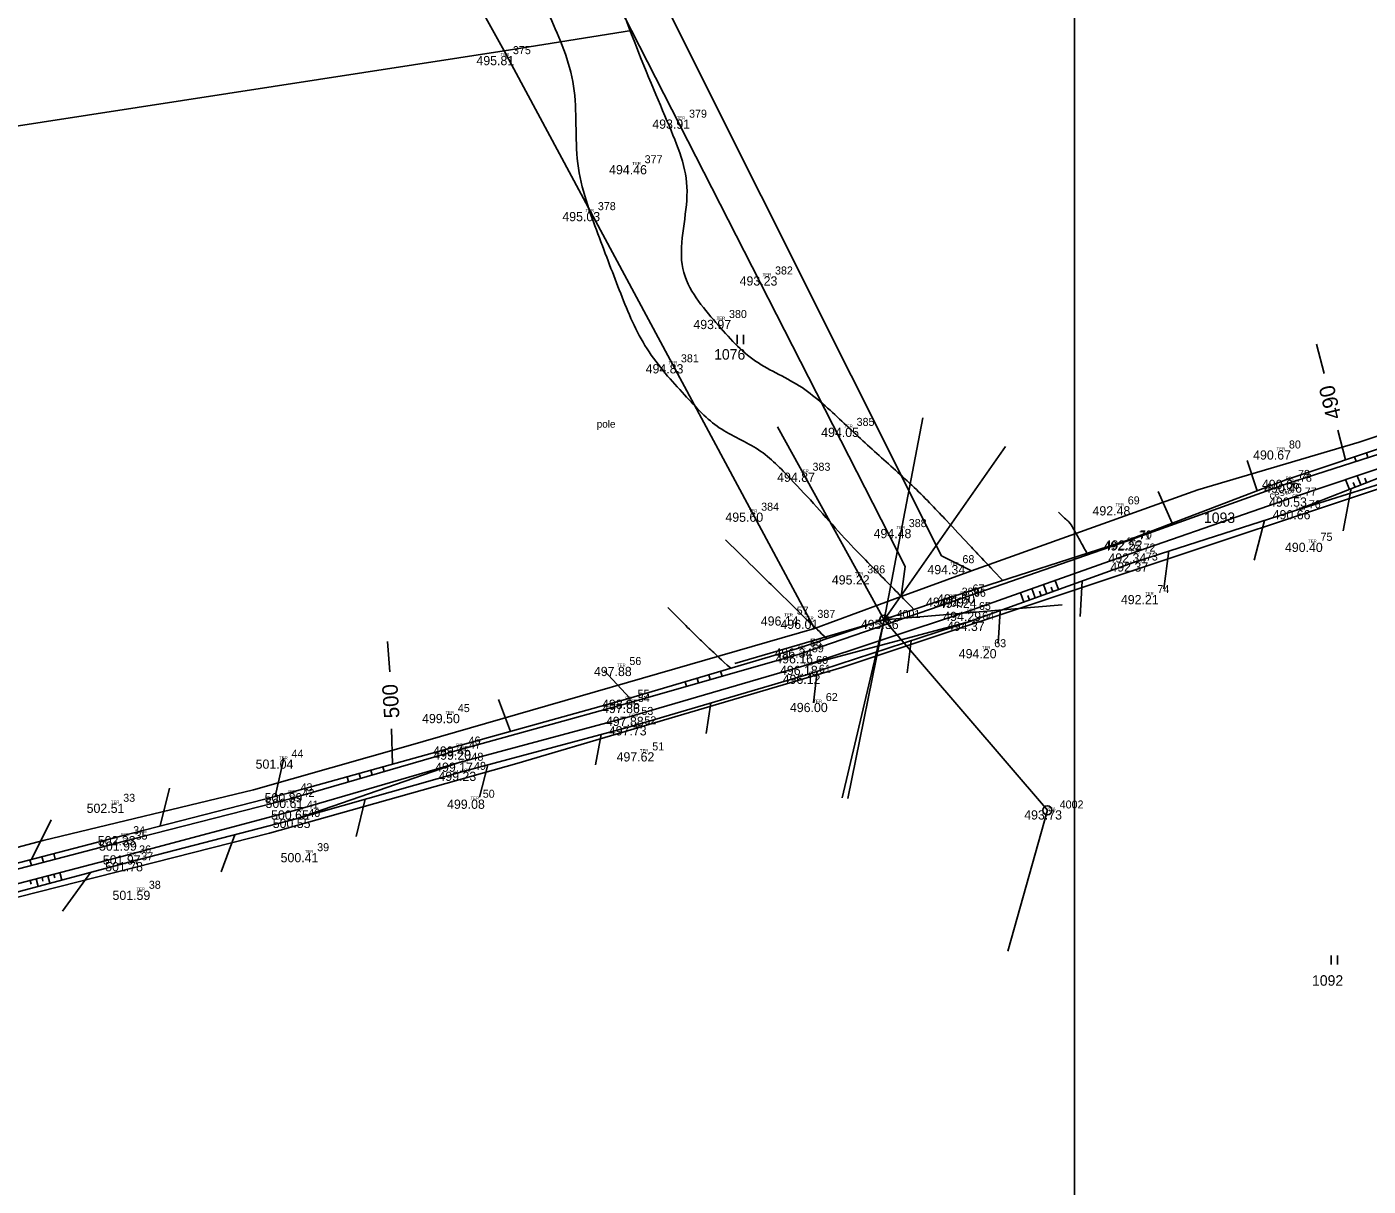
# Model space of a CAD drawing. Extents: x -604848 to -603227, y -1111879 to -1109838.
# Drawn here: x -603991.5 to -603773.6, y -1110531.9 to -1110343.6 of the extents above; entities that cross this region are included whole.
import ezdxf

# ---------------------------------------------------------------- set-up
doc = ezdxf.new("R2010")
doc.units = 0
for name, color, linetype in [('1', 7, 'Continuous'), ('10', 7, 'Continuous'), ('14', 7, 'Continuous'), ('18', 7, 'Continuous'), ('19', 7, 'Continuous'), ('20', 7, 'Continuous'), ('23', 7, 'Continuous'), ('4', 7, 'Continuous'), ('5', 7, 'Continuous'), ('7', 7, 'Continuous'), ('8', 7, 'Continuous'), ('9', 7, 'Continuous'), ('Default', 7, 'Continuous')]:
    doc.layers.add(name, color=color, linetype=linetype)

# ---------------------------------------------------------------- blocks, each defined once
blk = doc.blocks.new('Z3060')
at = {"layer": '23'}
for p, q in [((-0.5, 0), (-0.5, 1.5)), ((0.5, 1.5), (0.5, 0))]:
    blk.add_line(p, q, dxfattribs=at)
blk = doc.blocks.new('POINT_DISPLAY')
at = {"layer": 'Default'}
blk.add_line((0, 0), (0, 0), dxfattribs=at)
blk = doc.blocks.new('Z107')
at = {"layer": '5'}
for radius in [0.75, 0.01]:
    blk.add_circle((0, 0), radius, dxfattribs=at)

msp = doc.modelspace()

# ---------------------------------------------------------------- linework, layer by layer
at = {"layer": '1'}
for p, q in [((-603893.27, -1110344.22), (-603924.87, -1110281.49)), ((-603948.38, -1110285.5), (-603913.91, -1110347.53)), ((-603886.88, -1110341.74), (-603842.93, -1110429.54)), ((-603893.27, -1110344.22), (-603913.91, -1110347.53)), ((-603848.8, -1110431.28), (-603893.27, -1110344.22)), ((-603913.91, -1110347.53), (-604030.39, -1110365.48)), ((-603863.53, -1110441.33), (-603913.91, -1110347.53)), ((-603775.1, -1110411.08), (-603691.73, -1110383.39)), ((-603801.3, -1110418.83), (-603775.1, -1110411.08)), ((-603768.54, -1110417.48), (-603859.09, -1110447.69)), ((-603838.02, -1110431.98), (-603801.3, -1110418.83)), ((-603842.93, -1110429.54), (-603838.02, -1110431.98)), ((-603849.45, -1110436.14), (-603848.8, -1110431.28)), ((-603838.02, -1110431.98), (-603849.45, -1110436.14)), ((-603863.53, -1110441.33), (-603849.45, -1110436.14)), ((-603929.51, -1110460.39), (-603863.53, -1110441.33)), ((-603859.09, -1110447.69), (-603911.89, -1110463.24)), ((-603954.67, -1110467.55), (-603929.51, -1110460.39)), ((-603911.89, -1110463.24), (-603952.06, -1110474.57)), ((-603988.79, -1110475.77), (-603954.67, -1110467.55)), ((-604011.75, -1110481.89), (-603988.79, -1110475.77)), ((-603952.06, -1110474.57), (-603995.68, -1110485.67))]:
    msp.add_line(p, q, dxfattribs=at)
msp.add_lwpolyline([(-603227.31, -1110677.93), (-603227.31, -1109837.93), (-603821.31, -1109837.93), (-603821.31, -1110677.93), (-603227.31, -1110677.93)], dxfattribs=at)
at = {"layer": '10'}
for p, q in [((-603787.01, -1110417.17), (-603760.76, -1110408.43)), ((-603785.27, -1110422.1), (-603759.18, -1110413.94)), ((-603812.68, -1110427), (-603787.01, -1110417.17)), ((-603785.27, -1110422.1), (-603811.72, -1110430.59)), ((-603839.88, -1110435.77), (-603812.68, -1110427)), ((-603811.72, -1110430.59), (-603838.31, -1110440.22)), ((-603866.29, -1110444.57), (-603841.64, -1110436.3)), ((-603841.64, -1110436.3), (-603839.88, -1110435.77)), ((-603838.31, -1110440.22), (-603864.83, -1110448.83)), ((-603894.27, -1110452.88), (-603866.29, -1110444.57)), ((-603864.83, -1110448.83), (-603893.17, -1110457.2)), ((-603921.72, -1110460.48), (-603894.27, -1110452.88)), ((-603893.17, -1110457.2), (-603920.82, -1110464.59)), ((-603949, -1110468.06), (-603921.72, -1110460.48)), ((-603920.82, -1110464.59), (-603947.74, -1110472.24)), ((-603976.18, -1110475.04), (-603949, -1110468.06)), ((-603947.74, -1110472.24), (-603974.87, -1110479.27)), ((-604003.99, -1110482.33), (-603976.18, -1110475.04)), ((-603974.87, -1110479.27), (-604002.88, -1110486.76))]:
    msp.add_line(p, q, dxfattribs=at)
at = {"layer": '4'}
for p, q in [((-603786.7, -1110417.78), (-603760.5, -1110409.33)), ((-603759.82, -1110411.3), (-603785.93, -1110420.05)), ((-603812.84, -1110427.17), (-603786.7, -1110417.78)), ((-603785.93, -1110420.05), (-603812.1, -1110429.13)), ((-603839.65, -1110436.48), (-603812.84, -1110427.17)), ((-603812.1, -1110429.13), (-603838.83, -1110438.62)), ((-603865.97, -1110445.5), (-603839.65, -1110436.48)), ((-603838.83, -1110438.62), (-603865.27, -1110447.39)), ((-603894.22, -1110453.57), (-603865.97, -1110445.5)), ((-603865.27, -1110447.39), (-603893.65, -1110455.67)), ((-603921.64, -1110461.15), (-603894.22, -1110453.57)), ((-603893.65, -1110455.67), (-603921.25, -1110463.11)), ((-603948.69, -1110468.99), (-603921.64, -1110461.15)), ((-603921.25, -1110463.11), (-603947.98, -1110470.87)), ((-603975.79, -1110475.92), (-603948.69, -1110468.99)), ((-603947.98, -1110470.87), (-603975.22, -1110478.16)), ((-604003.75, -1110483.22), (-603975.79, -1110475.92)), ((-603975.22, -1110478.16), (-604003.19, -1110485.44))]:
    msp.add_line(p, q, dxfattribs=at)
at = {"layer": '5'}
for p, q in [((-603852.21, -1110439.92), (-603869.54, -1110408.59)), ((-603852.21, -1110439.92), (-603845.94, -1110407.11)), ((-603832.52, -1110411.78), (-603852.21, -1110439.92)), ((-603852.21, -1110439.92), (-603823.32, -1110437.51)), ((-603852.21, -1110439.92), (-603876.48, -1110447.04)), ((-603852.21, -1110439.92), (-603859.06, -1110468.86)), ((-603858.11, -1110468.96), (-603852.21, -1110439.92)), ((-603852.21, -1110439.92), (-603825.72, -1110470.86)), ((-603825.72, -1110470.86), (-603832.16, -1110493.72))]:
    msp.add_line(p, q, dxfattribs=at)
at = {"layer": '7'}
for p, q in [((-603780.76, -1110399.92), (-603782, -1110395.15)), ((-603778.53, -1110409.09), (-603777.29, -1110413.93)), ((-603785.27, -1110422.1), (-603759.68, -1110412.07)), ((-603791.66, -1110418.95), (-603793.27, -1110414.05)), ((-603805.43, -1110424.22), (-603807.73, -1110419.07)), ((-603776.36, -1110418.61), (-603777.69, -1110425.49)), ((-603790.46, -1110423.77), (-603792.13, -1110430.21)), ((-603805.97, -1110428.74), (-603806.8, -1110434.91)), ((-603820.08, -1110433.62), (-603820.39, -1110439.38)), ((-603833.4, -1110438.44), (-603833.69, -1110443.78)), ((-603838.31, -1110440.22), (-603865.27, -1110447.39)), ((-603932.49, -1110448.35), (-603932.89, -1110443.43)), ((-603847.86, -1110443.32), (-603848.5, -1110448.55)), ((-603893.52, -1110452.66), (-603897.69, -1110448.13)), ((-603863.08, -1110448.26), (-603863.7, -1110453.41)), ((-603912.92, -1110458.04), (-603914.88, -1110452.85)), ((-603880.36, -1110453.42), (-603881.14, -1110458.38)), ((-603932.05, -1110463.35), (-603932.23, -1110457.61)), ((-603898.19, -1110458.54), (-603899.12, -1110463.45)), ((-603951.14, -1110468.61), (-603949.73, -1110462.41)), ((-603921.25, -1110463.11), (-603947.74, -1110472.24)), ((-603916.59, -1110463.46), (-603917.93, -1110468.71)), ((-603969.8, -1110473.4), (-603968.3, -1110467.29)), ((-603936.52, -1110469.05), (-603937.98, -1110475.11)), ((-603990.67, -1110478.84), (-603987.49, -1110472.43)), ((-603957.7, -1110474.82), (-603959.88, -1110480.84)), ((-603981.06, -1110480.93), (-603985.64, -1110487.25))]:
    msp.add_line(p, q, dxfattribs=at)
for points in [[(-603832.97, -1110433.54), (-603835.87, -1110430.45), (-603838.77, -1110427.36), (-603841.67, -1110424.27), (-603847.26, -1110418.31), (-603853.48, -1110412.94), (-603859.43, -1110407.36), (-603865.68, -1110401.5), (-603873.96, -1110398.15), (-603879.7, -1110391.45), (-603886.92, -1110383.01), (-603882.86, -1110369.76), (-603887.08, -1110359.85), (-603893.83, -1110344.03), (-603899.3, -1110326.95), (-603910.93, -1110313.84), (-603919.05, -1110304.7), (-603927.68, -1110296.49), (-603936.23, -1110288.01), (-603942.66, -1110281.65), (-603949.71, -1110275.91), (-603956.03, -1110269.41), (-603962.97, -1110262.28), (-603958.28, -1110248.85), (-603963.99, -1110240.66), (-603968.51, -1110234.18), (-603973.41, -1110227.7), (-603979.81, -1110223.11), (-603983.65, -1110220.36), (-603987.5, -1110217.6), (-603991.34, -1110214.85)], [(-603847.4, -1110438.23), (-603849.93, -1110435.65), (-603852.46, -1110433.06), (-603854.99, -1110430.47), (-603859.22, -1110426.15), (-603863.16, -1110421.54), (-603867.31, -1110417.14), (-603872.27, -1110411.88), (-603879.33, -1110409.19), (-603884.37, -1110403.69), (-603891.25, -1110396.18), (-603895.06, -1110386.94), (-603898.56, -1110377.63), (-603902.93, -1110366.04), (-603901.59, -1110352.93), (-603906.69, -1110341.58), (-603910.59, -1110332.9), (-603915.37, -1110324.38), (-603922.34, -1110318.03), (-603928.71, -1110312.22), (-603935.08, -1110306.41), (-603941.45, -1110300.6)], [(-603819.28, -1110429.13), (-603820.03, -1110427.76), (-603820.78, -1110426.39), (-603821.54, -1110425.02), (-603822.1, -1110424), (-603823.12, -1110423.29), (-603823.92, -1110422.43)], [(-603861.54, -1110442.98), (-603862.81, -1110441.76), (-603864.11, -1110440.57), (-603865.36, -1110439.33), (-603869.57, -1110435.2), (-603873.78, -1110431.07), (-603877.98, -1110426.93)], [(-603877.15, -1110447.8), (-603878.71, -1110446.34), (-603880.3, -1110444.9), (-603881.83, -1110443.41), (-603883.7, -1110441.61), (-603885.52, -1110439.75), (-603887.36, -1110437.91)]]:
    msp.add_open_spline(points, degree=3, dxfattribs=at)
at = {"layer": '8'}
for p, q in [((-603775.82, -1110413.44), (-603775.57, -1110414.19)), ((-603773.92, -1110412.81), (-603773.67, -1110413.57)), ((-603776.67, -1110418.73), (-603777.29, -1110417.15)), ((-603775.74, -1110418.37), (-603776.04, -1110417.6)), ((-603774.81, -1110418), (-603775.39, -1110416.52)), ((-603773.88, -1110417.64), (-603774.16, -1110416.92)), ((-603827.68, -1110436.37), (-603828.23, -1110434.85)), ((-603825.8, -1110435.69), (-603826.34, -1110434.19)), ((-603824.86, -1110435.35), (-603825.13, -1110434.6)), ((-603823.92, -1110435), (-603824.46, -1110433.52)), ((-603829.56, -1110437.05), (-603830.11, -1110435.52)), ((-603828.62, -1110436.71), (-603828.89, -1110435.95)), ((-603826.74, -1110436.03), (-603827.01, -1110435.27)), ((-603878.79, -1110448.28), (-603878.55, -1110449.09)), ((-603884.54, -1110449.99), (-603884.32, -1110450.74)), ((-603882.62, -1110449.42), (-603882.4, -1110450.19)), ((-603880.71, -1110448.85), (-603880.47, -1110449.64)), ((-603939.43, -1110465.4), (-603939.2, -1110466.24)), ((-603937.5, -1110464.87), (-603937.27, -1110465.68)), ((-603935.57, -1110464.33), (-603935.35, -1110465.12)), ((-603933.65, -1110463.79), (-603933.43, -1110464.57)), ((-603989.01, -1110478.4), (-603988.77, -1110479.31)), ((-603987.08, -1110477.9), (-603986.84, -1110478.81)), ((-603990.94, -1110478.91), (-603990.71, -1110479.82)), ((-603990.92, -1110482.24), (-603990.76, -1110482.86)), ((-603989.95, -1110481.99), (-603989.63, -1110483.22)), ((-603988.98, -1110481.74), (-603988.83, -1110482.35)), ((-603988.02, -1110481.49), (-603987.7, -1110482.7)), ((-603987.05, -1110481.24), (-603986.89, -1110481.84)), ((-603986.08, -1110480.98), (-603985.77, -1110482.19))]:
    msp.add_line(p, q, dxfattribs=at)

# ---------------------------------------------------------------- block references
at = {"layer": '18'}
for p in [(-603914.51, -1110348.34), (-603885.91, -1110358.66), (-603893.12, -1110366.06), (-603900.72, -1110373.68), (-603871.95, -1110384.13), (-603879.42, -1110391.2), (-603887.23, -1110398.4), (-603858.7, -1110408.72), (-603788.49, -1110412.4), (-603865.86, -1110416.01), (-603787.01, -1110417.17), (-603786.7, -1110417.78), (-603814.66, -1110421.47), (-603785.93, -1110420.05), (-603785.27, -1110422.1), (-603874.2, -1110422.5), (-603850.23, -1110425.16), (-603812.84, -1110427.17), (-603812.68, -1110427), (-603783.36, -1110427.4), (-603812.1, -1110429.13), (-603811.72, -1110430.59), (-603856.97, -1110432.68), (-603841.51, -1110431.02), (-603841.64, -1110436.3), (-603839.88, -1110435.77), (-603839.65, -1110436.48), (-603809.85, -1110435.89), (-603868.43, -1110439.37), (-603838.83, -1110438.62), (-603865.07, -1110439.9), (-603852.21, -1110439.92), (-603838.31, -1110440.22), (-603866.29, -1110444.57), (-603865.97, -1110445.5), (-603836.35, -1110444.67), (-603895.6, -1110447.56), (-603865.27, -1110447.39), (-603864.83, -1110448.83), (-603894.27, -1110452.88), (-603894.22, -1110453.57), (-603863.7, -1110453.41), (-603923.46, -1110455.21), (-603893.65, -1110455.67), (-603893.17, -1110457.2), (-603921.72, -1110460.48), (-603921.64, -1110461.15), (-603950.47, -1110462.61), (-603921.25, -1110463.11), (-603891.88, -1110461.43), (-603920.82, -1110464.59), (-603977.8, -1110469.78), (-603949, -1110468.06), (-603948.69, -1110468.99), (-603919.41, -1110469.12), (-603947.98, -1110470.87), (-603947.74, -1110472.24), (-603825.72, -1110470.86), (-603976.18, -1110475.04), (-603975.79, -1110475.92), (-603975.22, -1110478.16), (-603946.3, -1110477.8), (-603974.87, -1110479.27), (-603973.64, -1110483.92)]:
    msp.add_blockref('POINT_DISPLAY', p, dxfattribs=at)
at = {"layer": '23'}
for p in [(-603875.59, -1110395.15), (-603779.11, -1110495.93)]:
    msp.add_blockref('Z3060', p, dxfattribs=at)
at = {"layer": '5'}
for p in [(-603852.21, -1110439.92), (-603825.72, -1110470.86)]:
    msp.add_blockref('Z107', p, dxfattribs=at)

# ---------------------------------------------------------------- texts
at = {"layer": '14'}
for s, p in [('1076', (-603879.84, -1110397.66)), ('1093', (-603800.29, -1110424.19)), ('1092', (-603782.74, -1110499.35))]:
    msp.add_text(s, height=1.7, dxfattribs=at).set_placement(p)
at = {"layer": '18'}
for s, p in [('TER', (-603914.51, -1110348.34)), ('TER', (-603885.91, -1110358.66)), ('TER', (-603893.12, -1110366.06)), ('TER', (-603900.72, -1110373.68)), ('TER', (-603871.95, -1110384.13)), ('TER', (-603879.42, -1110391.2)), ('TER', (-603887.23, -1110398.4)), ('TER', (-603858.7, -1110408.72)), ('TER', (-603788.49, -1110412.4)), ('TER', (-603865.86, -1110416.01)), ('POL', (-603787.01, -1110417.17)), ('CES', (-603786.7, -1110417.78)), ('CES', (-603785.93, -1110420.05)), ('TER', (-603874.2, -1110422.5)), ('TER', (-603814.66, -1110421.47)), ('LOU', (-603785.27, -1110422.1)), ('TER', (-603850.23, -1110425.16)), ('POL', (-603812.68, -1110427)), ('CES', (-603812.84, -1110427.17)), ('CES', (-603812.1, -1110429.13)), ('TER', (-603783.36, -1110427.4)), ('TER', (-603841.51, -1110431.02)), ('LOU', (-603811.72, -1110430.59)), ('TER', (-603856.97, -1110432.68)), ('POL', (-603841.64, -1110436.3)), ('POL', (-603839.88, -1110435.77)), ('CES', (-603839.65, -1110436.48)), ('TER', (-603809.85, -1110435.89)), ('TER', (-603868.43, -1110439.37)), ('TER', (-603865.07, -1110439.9)), ('STA', (-603852.21, -1110439.92)), ('CES', (-603838.83, -1110438.62)), ('LOU', (-603838.31, -1110440.22)), ('POL', (-603866.29, -1110444.57)), ('CES', (-603865.97, -1110445.5)), ('TER', (-603836.35, -1110444.67)), ('TER', (-603895.6, -1110447.56)), ('CES', (-603865.27, -1110447.39)), ('LOU', (-603864.83, -1110448.83)), ('POL', (-603894.27, -1110452.88)), ('TER', (-603923.46, -1110455.21)), ('CES', (-603894.22, -1110453.57)), ('TER', (-603863.7, -1110453.41)), ('CES', (-603893.65, -1110455.67)), ('LOU', (-603893.17, -1110457.2)), ('POL', (-603921.72, -1110460.48)), ('CES', (-603921.64, -1110461.15)), ('TER', (-603891.88, -1110461.43)), ('TER', (-603950.47, -1110462.61)), ('CES', (-603921.25, -1110463.11)), ('LOU', (-603920.82, -1110464.59)), ('POL', (-603949, -1110468.06)), ('TER', (-603977.8, -1110469.78)), ('CES', (-603948.69, -1110468.99)), ('TER', (-603919.41, -1110469.12)), ('CES', (-603947.98, -1110470.87)), ('LOU', (-603947.74, -1110472.24)), ('STA', (-603825.72, -1110470.86)), ('POL', (-603976.18, -1110475.04)), ('CES', (-603975.79, -1110475.92)), ('CES', (-603975.22, -1110478.16)), ('LOU', (-603974.87, -1110479.27)), ('TER', (-603946.3, -1110477.8)), ('TER', (-603973.64, -1110483.92))]:
    msp.add_text(s, height=0.5, dxfattribs=at).set_placement(p)
at = {"layer": '19'}
for s, p in [('375', (-603912.51, -1110348.04)), ('379', (-603883.91, -1110358.36)), ('377', (-603891.12, -1110365.76)), ('378', (-603898.72, -1110373.38)), ('382', (-603869.95, -1110383.83)), ('380', (-603877.42, -1110390.9)), ('381', (-603885.23, -1110398.1)), ('385', (-603856.7, -1110408.42)), ('80', (-603786.49, -1110412.09)), ('383', (-603863.86, -1110415.71)), ('79', (-603785.01, -1110416.87)), ('78', (-603784.7, -1110417.48)), ('69', (-603812.66, -1110421.17)), ('77', (-603783.93, -1110419.75)), ('384', (-603872.2, -1110422.2)), ('76', (-603783.27, -1110421.8)), ('388', (-603848.23, -1110424.86)), ('71', (-603810.84, -1110426.87)), ('70', (-603810.68, -1110426.7)), ('75', (-603781.36, -1110427.09)), ('72', (-603810.1, -1110428.83)), ('68', (-603839.51, -1110430.72)), ('73', (-603809.72, -1110430.29)), ('386', (-603854.97, -1110432.38)), ('389', (-603839.64, -1110436)), ('67', (-603837.88, -1110435.47)), ('66', (-603837.65, -1110436.18)), ('74', (-603807.85, -1110435.59)), ('65', (-603836.83, -1110438.32)), ('57', (-603866.43, -1110439.07)), ('387', (-603863.07, -1110439.6)), ('4001', (-603850.21, -1110439.62)), ('64', (-603836.31, -1110439.92)), ('58', (-603864.29, -1110444.27)), ('59', (-603863.97, -1110445.2)), ('63', (-603834.35, -1110444.37)), ('56', (-603893.6, -1110447.26)), ('60', (-603863.27, -1110447.09)), ('61', (-603862.83, -1110448.53)), ('55', (-603892.27, -1110452.58)), ('54', (-603892.22, -1110453.27)), ('62', (-603861.7, -1110453.11)), ('45', (-603921.46, -1110454.91)), ('53', (-603891.65, -1110455.37)), ('52', (-603891.17, -1110456.9)), ('46', (-603919.72, -1110460.18)), ('44', (-603948.47, -1110462.31)), ('47', (-603919.64, -1110460.85)), ('51', (-603889.88, -1110461.13)), ('48', (-603919.25, -1110462.81)), ('49', (-603918.82, -1110464.29)), ('43', (-603947, -1110467.77)), ('42', (-603946.69, -1110468.69)), ('50', (-603917.41, -1110468.82)), ('33', (-603975.8, -1110469.48)), ('41', (-603945.98, -1110470.57)), ('4002', (-603823.72, -1110470.56)), ('40', (-603945.74, -1110471.94)), ('34', (-603974.18, -1110474.74)), ('35', (-603973.79, -1110475.62)), ('36', (-603973.22, -1110477.86)), ('39', (-603944.3, -1110477.5)), ('37', (-603972.87, -1110478.97)), ('38', (-603971.64, -1110483.61))]:
    msp.add_text(s, height=1.3, dxfattribs=at).set_placement(p)
at = {"layer": '20'}
for s, p in [('495.81 ', (-603918.44, -1110349.84)), ('493.91 ', (-603889.88, -1110360.16)), ('494.46 ', (-603896.89, -1110367.56)), ('495.03 ', (-603904.49, -1110375.18)), ('493.23 ', (-603875.7, -1110385.63)), ('493.97 ', (-603883.21, -1110392.7)), ('494.83 ', (-603890.96, -1110399.9)), ('494.05 ', (-603862.45, -1110410.22)), ('490.67 ', (-603792.3, -1110413.9)), ('494.87 ', (-603869.6, -1110417.51)), ('490.66 ', (-603790.88, -1110418.67)), ('490.46 ', (-603790.51, -1110419.28)), ('492.48 ', (-603818.39, -1110422.97)), ('490.53 ', (-603789.71, -1110421.55)), ('490.66 ', (-603789.13, -1110423.6)), ('495.60 ', (-603878.01, -1110424)), ('494.48 ', (-603853.94, -1110426.66)), ('492.25 ', (-603816.59, -1110428.67)), ('492.52 ', (-603816.42, -1110428.5)), ('490.40 ', (-603787.14, -1110428.9)), ('492.34 ', (-603815.8, -1110430.63)), ('492.37 ', (-603815.48, -1110432.09)), ('495.22 ', (-603860.72, -1110434.18)), ('494.34 ', (-603845.2, -1110432.52)), ('494.59 ', (-603845.42, -1110437.8)), ('494.50 ', (-603843.64, -1110437.27)), ('494.24 ', (-603843.34, -1110437.98)), ('492.21 ', (-603813.78, -1110437.39)), ('496.14 ', (-603872.26, -1110440.87)), ('494.29 ', (-603842.62, -1110440.12)), ('496.01 ', (-603869.06, -1110441.4)), ('495.36 ', (-603856.01, -1110441.42)), ('494.37 ', (-603842.04, -1110441.72)), ('496.34 ', (-603870.03, -1110446.07)), ('496.16 ', (-603869.91, -1110447)), ('494.20 ', (-603840.11, -1110446.17)), ('497.88 ', (-603899.36, -1110449.06)), ('496.18 ', (-603869.14, -1110448.89)), ('496.12 ', (-603868.71, -1110450.33)), ('497.86 ', (-603898.04, -1110455.07)), ('498.05 ', (-603898.04, -1110454.38)), ('496.00 ', (-603867.53, -1110454.91)), ('499.50 ', (-603927.27, -1110456.71)), ('497.88 ', (-603897.41, -1110457.17)), ('497.73 ', (-603896.94, -1110458.7)), ('499.45 ', (-603925.49, -1110461.98)), ('499.20 ', (-603925.45, -1110462.65)), ('501.04 ', (-603954.3, -1110464.11)), ('499.17 ', (-603925.14, -1110464.61)), ('497.62 ', (-603895.68, -1110462.93)), ('499.23 ', (-603924.61, -1110466.09)), ('502.51 ', (-603981.74, -1110471.28)), ('500.89 ', (-603952.84, -1110469.56)), ('500.61 ', (-603952.69, -1110470.49)), ('499.08 ', (-603923.21, -1110470.62)), ('500.65 ', (-603951.79, -1110472.37)), ('500.55 ', (-603951.52, -1110473.74)), ('493.73 ', (-603829.48, -1110472.36)), ('502.33 ', (-603979.93, -1110476.54)), ('501.99 ', (-603979.73, -1110477.42)), ('501.97 ', (-603979.11, -1110479.66)), ('500.41 ', (-603950.24, -1110479.3)), ('501.78 ', (-603978.73, -1110480.77)), ('501.59 ', (-603977.54, -1110485.42))]:
    msp.add_text(s, height=1.5, dxfattribs=at).set_placement(p)
at = {"layer": '7'}
for s, rotation, p in [('490', 103.5, (-603777.93, -1110407.04)), ('500', 93.6, (-603930.93, -1110455.85))]:
    msp.add_text(s, height=2.5, rotation=rotation, dxfattribs=at).set_placement(p)
at = {"layer": '9'}
msp.add_text('pole', height=1.2, dxfattribs=at).set_placement((-603898.9, -1110408.71))
msp.add_text('cesta', height=1.2, rotation=18, dxfattribs=at).set_placement((-603789.47, -1110420.42))

doc.saveas('drawing.dxf')
